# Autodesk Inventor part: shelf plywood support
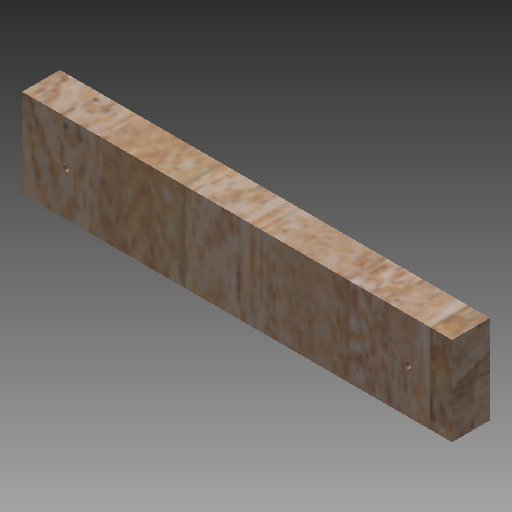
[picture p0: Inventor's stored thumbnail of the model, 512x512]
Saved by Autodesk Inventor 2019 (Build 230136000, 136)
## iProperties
Created: 2013-07
Part Number: shelf plywood support
Material: Generic
Document SubType Name: Modeling
Designer: Patrick Rice
Density: 1 g/cm^3
Appearance: Red Oak - Natural
Author: Patrick Rice
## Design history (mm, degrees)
sketch "Sketch1"
  geometry: L1 (44.45, -19.05)-(-44.45, -19.05); L2 (-44.45, -19.05)-(-44.45, 19.05); L3 (-44.45, 19.05)-(44.45, 19.05); L4 (44.45, 19.05)-(44.45, -19.05); L5 (44.45, -19.05)-(-44.45, 19.05); L6 (-44.45, -19.05)-(44.45, 19.05); 1 further point
  constraints: 12 end point, 2 midpoint, 2 parallel, 1 horizontal, 1 perpendicular
  dimensions: "d0" = 88.9 distance of L2.end L3.end; "d1" = 38.1 distance of L1.end L2.end
extrude "Extrusion1" new body sketch "Sketch1" distance "d2" = 431.8; taper "d3" = 0 deg
hole "Hole1" diameter "d6" = 6.35; stored, may be unused: countersink angle "d10" = 82 deg, drill point angle "d12" = 118 deg; dims "d4" = 44.45, "d5" = 44.45, "d7" = 19.05, "d8" = 19.05, "d9" = 12.7, "d11" = 25.4
hole "Hole2" diameter "d15" = 6.35; stored, may be unused: countersink angle "d19" = 82 deg, drill point angle "d21" = 118 deg; dims "d13" = 44.45, "d14" = 44.45, "d16" = 19.05, "d17" = 19.05, "d18" = 12.7, "d20" = 25.4
body "Solid1"
